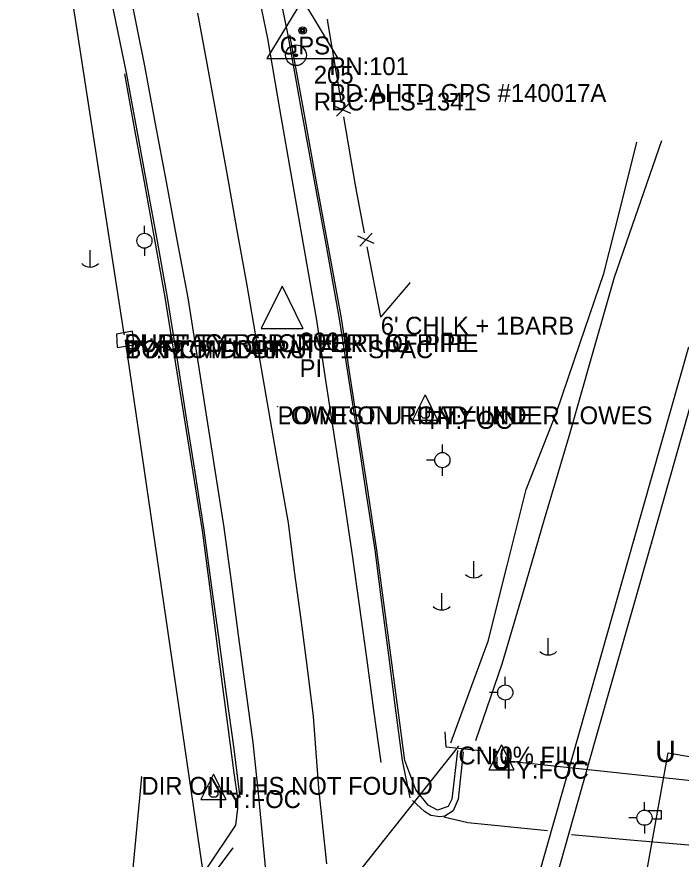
# Model space of a CAD drawing. Extents: x 929765 to 934279, y 1533086 to 1541189.
# Drawn here: x 931911.3 to 932097.7, y 1537538.1 to 1537774.2 of the extents above; entities that cross this region are included whole.
import ezdxf

# ---------------------------------------------------------------- set-up
doc = ezdxf.new("R2010")
doc.units = 0
for name, color, linetype in [('Default', 7, 'Continuous'), ('S_CAL_CORNER', 7, 'Continuous'), ('S_CAL_CORNER_ANNOT', 7, 'Continuous'), ('S_CROSS_DRAIN', 7, 'Continuous'), ('S_CROSS_DRAIN_ANNOT', 7, 'Continuous'), ('S_CURB', 7, 'Continuous'), ('S_DITCHLINE', 7, 'Continuous'), ('S_DRG_PT_SYM', 7, 'Continuous'), ('S_DROP_INLET_ANNOT', 7, 'Continuous'), ('S_EDGE_CONCRETE', 7, 'Continuous'), ('S_EDGE_PAVEMENT', 7, 'Continuous'), ('S_ELECTRIC_UTILITIES_ANNOT', 7, 'Continuous'), ('S_FENCE', 7, 'Continuous'), ('S_FENCE_ANNOT', 7, 'Continuous'), ('S_HEADWALL', 7, 'Continuous'), ('S_IRON_PIN', 7, 'Continuous'), ('S_IRON_PIN_ANNOT', 7, 'Continuous'), ('S_MANHOLE_ANNOT', 7, 'Continuous'), ('S_MSC_PT_SYM', 7, 'Continuous'), ('S_PAVEMENT_CROWN', 7, 'Continuous'), ('S_PRIMARY_CTL', 7, 'Continuous'), ('S_PRIMARY_CTL_ANNOT', 7, 'Continuous'), ('S_RAILROAD', 7, 'Continuous'), ('S_SANITARY_SEWER', 7, 'Continuous'), ('S_SANITARY_SEWER_ANNOT', 7, 'Continuous'), ('S_SHOULDER', 7, 'Continuous'), ('S_STORM_SEWER', 7, 'Continuous'), ('S_STORM_SEWER_ANNOT', 7, 'Continuous'), ('S_SURVEY_TEXT_ANNOT', 7, 'Continuous'), ('S_UNDERGROUND_CABLE', 7, 'Continuous'), ('S_UTILITY_POLE', 7, 'Continuous'), ('S_UTILITY_POLE_ANNOT', 7, 'Continuous'), ('S_UTL_PT_SYM', 7, 'Continuous')]:
    doc.layers.add(name, color=color, linetype=linetype)

msp = doc.modelspace()

# ---------------------------------------------------------------- linework, layer by layer
at = {"layer": 'S_CAL_CORNER'}
for p, q in [((931985.74, 1537698.67), (931979.86, 1537686.85)), ((931985.74, 1537698.67), (931991.55, 1537686.85)), ((931979.86, 1537686.85), (931991.55, 1537686.85))]:
    msp.add_line(p, q, dxfattribs=at)
at = {"layer": 'S_CROSS_DRAIN'}
msp.add_line((931974.13, 1537492.75), (932035.18, 1537569.61), dxfattribs=at)
at = {"layer": 'S_CURB'}
for points in [[(932034.94, 1537568.49), (932033.32, 1537554.86), (932032.3, 1537552.8), (932029.35, 1537551.77), (932026.7, 1537553.15), (932023.25, 1537557.47), (932020.17, 1537565.75), (932018.21, 1537580.48), (932016.25, 1537595.21), (932014.29, 1537609.94), (932012.33, 1537624.67), (932009.84, 1537640.95), (932007.35, 1537657.22), (932004.86, 1537673.5), (932002.37, 1537689.77), (931998.76, 1537709.63), (931995.14, 1537729.49), (931991.53, 1537749.35), (931987.91, 1537769.21)], [(931951.42, 1537526.31), (931964.23, 1537534.86), (931972.76, 1537547.6), (931973.29, 1537552.29), (931973.36, 1537555.14), (931972.31, 1537562.3), (931970.08, 1537579.27), (931967.84, 1537596.25), (931965.61, 1537613.23), (931963.38, 1537630.2), (931960.78, 1537646.56), (931958.18, 1537662.91), (931955.58, 1537679.26), (931952.98, 1537695.61), (931950.14, 1537711.26), (931947.3, 1537726.92), (931944.46, 1537742.57), (931941.62, 1537758.23)]]:
    msp.add_lwpolyline(points, dxfattribs=at)
at = {"layer": 'S_DITCHLINE'}
for points in [[(932033.11, 1537570.71), (932038.34, 1537584.92), (932043.57, 1537599.13), (932048.86, 1537620.42), (932054.15, 1537641.7), (932062.73, 1537663.29), (932069.33, 1537682.77), (932075.94, 1537702.25), (932080.61, 1537720.66), (932085.27, 1537739.06)], [(932040.04, 1537571.29), (932047.46, 1537592.84), (932053.4, 1537613.09), (932059.34, 1537633.33), (932066.26, 1537656.63), (932072.62, 1537678.94), (932078.98, 1537701.25), (932085.6, 1537720.38), (932092.23, 1537739.52)]]:
    msp.add_lwpolyline(points, dxfattribs=at)
at = {"layer": 'S_DRG_PT_SYM'}
for points in [[(931941.81, 1537683.51), (931941.81, 1537683.56), (931941.81, 1537683.51), (931941.76, 1537683.51), (931941.81, 1537683.51), (931941.81, 1537683.46), (931941.81, 1537683.51), (931941.86, 1537683.51)], [(932035.18, 1537569.61), (932035.18, 1537569.66), (932035.18, 1537569.61), (932035.13, 1537569.61), (932035.18, 1537569.61), (932035.18, 1537569.56), (932035.18, 1537569.61), (932035.23, 1537569.61)]]:
    msp.add_lwpolyline(points, dxfattribs=at)
at = {"layer": 'S_EDGE_CONCRETE'}
msp.add_lwpolyline([(931944.22, 1537682.23), (931943.79, 1537686.04), (931939.28, 1537685.21), (931939.51, 1537681.54)], close=True, dxfattribs=at)
msp.add_lwpolyline([(932036.56, 1537568.15), (932035.14, 1537554.86), (932033.7, 1537551.61), (932031.36, 1537550.12), (932029.97, 1537549.91), (932027.45, 1537550.32), (932025.68, 1537551.39), (932022.31, 1537554.46)], dxfattribs=at)
at = {"layer": 'S_EDGE_PAVEMENT'}
for points in [[(931981.22, 1537534.96), (931979.16, 1537556.54), (931977.64, 1537570.72), (931975.6, 1537585.79), (931973.55, 1537600.86), (931971.51, 1537615.93), (931969.46, 1537631), (931966.94, 1537647.11), (931964.42, 1537663.22), (931961.89, 1537679.33), (931959.37, 1537695.44), (931956.33, 1537711.7), (931953.29, 1537727.95), (931950.25, 1537744.2), (931947.21, 1537760.45), (931942.74, 1537782.82), (931938.28, 1537805.2), (931934.64, 1537822.05), (931931, 1537838.9), (931927.36, 1537855.75), (931923.72, 1537872.6), (931920.41, 1537886.31), (931917.1, 1537900.03)], [(932013.54, 1537565.12), (932011.5, 1537579.83), (932009.47, 1537594.54), (932007.44, 1537609.25), (932005.4, 1537623.96), (932002.92, 1537640.28), (932000.43, 1537656.59), (931997.95, 1537672.9), (931995.46, 1537689.21), (931992.02, 1537708.93), (931988.58, 1537728.65), (931985.14, 1537748.37), (931981.7, 1537768.09), (931979.05, 1537781.28), (931976.4, 1537794.47), (931973.75, 1537807.66), (931971.1, 1537820.85), (931967.73, 1537835.84), (931964.36, 1537850.82), (931961, 1537865.81), (931957.63, 1537880.8), (931954.49, 1537894.12)], [(932060.14, 1537545.98), (932037.8, 1537548.24), (932031.11, 1537549.86)], [(932132.45, 1537539.14), (932116.07, 1537540.56), (932099.7, 1537541.99), (932083.32, 1537543.41), (932066.94, 1537544.83)], [(931953.05, 1537524.89), (931963.67, 1537532.14), (931967.87, 1537535.71), (931972.01, 1537541.26)]]:
    msp.add_lwpolyline(points, dxfattribs=at)
at = {"layer": 'S_FENCE'}
for p, q in [((932000.96, 1537746.38), (932004.51, 1537749.9)), ((932000.96, 1537746.38), (932004.51, 1537749.9)), ((932005, 1537747.07), (932000.48, 1537749.21)), ((932005, 1537747.07), (932000.48, 1537749.21)), ((932011.54, 1537710.7), (932006.97, 1537712.74)), ((932011.54, 1537710.7), (932006.97, 1537712.74)), ((932007.51, 1537709.93), (932011, 1537713.52)), ((932007.51, 1537709.93), (932011, 1537713.52))]:
    msp.add_line(p, q, dxfattribs=at)
for points in [[(932002.4, 1537750.11), (931998.44, 1537773.39)], [(932002.4, 1537750.11), (931998.44, 1537773.39)], [(932006.42, 1537726.45), (932003.07, 1537746.17)], [(932006.42, 1537726.45), (932003.07, 1537746.17)], [(932008.88, 1537713.69), (932006.42, 1537726.45)], [(932008.88, 1537713.69), (932006.42, 1537726.45)], [(932013.41, 1537690.12), (932009.63, 1537709.76)], [(932013.41, 1537690.12), (932009.63, 1537709.76)], [(932021.53, 1537699.62), (932013.41, 1537690.12)], [(932021.53, 1537699.62), (932013.41, 1537690.12)]]:
    msp.add_lwpolyline(points, dxfattribs=at)
at = {"layer": 'S_HEADWALL'}
msp.add_lwpolyline([(932042.11, 1537568.36), (932031.77, 1537569.49), (932031.45, 1537573.75)], dxfattribs=at)
at = {"layer": 'S_IRON_PIN'}
for radius in [2.91, 0.411, 0.262, 0.212, 0.145, 0.0822, 0.0581]:
    msp.add_circle((931989.63, 1537763.45), radius, dxfattribs=at)
at = {"layer": 'S_MSC_PT_SYM'}
for points in [[(931998.44, 1537773.39), (931998.44, 1537773.44), (931998.44, 1537773.39), (931998.39, 1537773.39), (931998.44, 1537773.39), (931998.44, 1537773.34), (931998.44, 1537773.39), (931998.49, 1537773.39)], [(932006.42, 1537726.45), (932006.42, 1537726.5), (932006.42, 1537726.45), (932006.37, 1537726.45), (932006.42, 1537726.45), (932006.42, 1537726.4), (932006.42, 1537726.45), (932006.47, 1537726.45)], [(932021.53, 1537699.62), (932021.53, 1537699.67), (932021.53, 1537699.62), (932021.48, 1537699.62), (932021.53, 1537699.62), (932021.53, 1537699.57), (932021.53, 1537699.62), (932021.58, 1537699.62)], [(932013.41, 1537690.12), (932013.41, 1537690.17), (932013.41, 1537690.12), (932013.36, 1537690.12), (932013.41, 1537690.12), (932013.41, 1537690.07), (932013.41, 1537690.12), (932013.46, 1537690.12)], [(931941.47, 1537685.23), (931941.47, 1537685.28), (931941.47, 1537685.23), (931941.42, 1537685.23), (931941.47, 1537685.23), (931941.47, 1537685.18), (931941.47, 1537685.23), (931941.52, 1537685.23)], [(931984.48, 1537664.99), (931984.48, 1537665.04), (931984.48, 1537664.99), (931984.43, 1537664.99), (931984.48, 1537664.99), (931984.48, 1537664.94), (931984.48, 1537664.99), (931984.53, 1537664.99)], [(932084.46, 1537627.73), (932084.46, 1537627.78), (932084.46, 1537627.73), (932084.41, 1537627.73), (932084.46, 1537627.73), (932084.46, 1537627.68), (932084.46, 1537627.73), (932084.51, 1537627.73)], [(932089.34, 1537626.62), (932089.34, 1537626.67), (932089.34, 1537626.62), (932089.29, 1537626.62), (932089.34, 1537626.62), (932089.34, 1537626.57), (932089.34, 1537626.62), (932089.39, 1537626.62)], [(932069.38, 1537574.33), (932069.38, 1537574.38), (932069.38, 1537574.33), (932069.33, 1537574.33), (932069.38, 1537574.33), (932069.38, 1537574.28), (932069.38, 1537574.33), (932069.43, 1537574.33)], [(932073.74, 1537571.91), (932073.74, 1537571.96), (932073.74, 1537571.91), (932073.69, 1537571.91), (932073.74, 1537571.91), (932073.74, 1537571.86), (932073.74, 1537571.91), (932073.79, 1537571.91)]]:
    msp.add_lwpolyline(points, dxfattribs=at)
at = {"layer": 'S_PAVEMENT_CROWN'}
msp.add_lwpolyline([(931998.24, 1537536.73), (931996.02, 1537557.94), (931994.59, 1537578.02), (931992.82, 1537591.62), (931991.04, 1537605.21), (931989.26, 1537618.8), (931987.49, 1537632.39), (931984.58, 1537649.15), (931981.68, 1537665.91), (931978.77, 1537682.67), (931975.87, 1537699.43), (931973.08, 1537714.85), (931970.29, 1537730.26), (931967.5, 1537745.68), (931964.71, 1537761.1), (931962.08, 1537775.23)], dxfattribs=at)
at = {"layer": 'S_PRIMARY_CTL'}
for p, q in [((931991.5, 1537779.07), (931981.47, 1537762.56)), ((931991.5, 1537779.07), (932001.33, 1537762.56)), ((931981.47, 1537762.56), (932001.33, 1537762.56))]:
    msp.add_line(p, q, dxfattribs=at)
for radius in [1.04, 0.609, 0.344]:
    msp.add_circle((931991.5, 1537770.37), radius, dxfattribs=at)
at = {"layer": 'S_RAILROAD'}
for p, q in [((932084.46, 1537627.73), (932099.81, 1537681.72)), ((932089.34, 1537626.62), (932104.37, 1537679.83)), ((932069.38, 1537574.33), (932084.46, 1537627.73)), ((932073.74, 1537571.91), (932089.34, 1537626.62)), ((932053.49, 1537518.73), (932069.38, 1537574.33)), ((932058.32, 1537517.56), (932073.74, 1537571.91)), ((932087.37, 1537551.78), (932087.37, 1537554.03)), ((932092.17, 1537551.63), (932088.3, 1537551.63)), ((932092.17, 1537549.3), (932092.17, 1537551.63)), ((932085.27, 1537549.65), (932082.95, 1537549.65)), ((932092.17, 1537549.3), (932089.46, 1537549.3)), ((932087.44, 1537545.23), (932087.44, 1537547.56))]:
    msp.add_line(p, q, dxfattribs=at)
msp.add_circle((932087.37, 1537549.67), 2.13, dxfattribs=at)
at = {"layer": 'S_SANITARY_SEWER'}
msp.add_line((931946.28, 1537561.11), (931939.08, 1537485.09), dxfattribs=at)
at = {"layer": 'S_SHOULDER'}
for points in [[(931973.95, 1537555.3), (931972.29, 1537569.03), (931970.18, 1537584.34), (931968.08, 1537599.65), (931965.97, 1537614.96), (931963.87, 1537630.27), (931961.31, 1537646.59), (931958.75, 1537662.9), (931956.19, 1537679.22), (931953.63, 1537695.53), (931950.75, 1537711.28), (931947.86, 1537727.03), (931944.98, 1537742.78), (931942.1, 1537758.53), (931937.34, 1537781.66), (931932.57, 1537804.8), (931928.93, 1537821.29), (931925.29, 1537837.78), (931921.65, 1537854.27), (931918.01, 1537870.76), (931914.67, 1537884.32), (931911.34, 1537897.89)], [(932021.69, 1537555.26), (932019.48, 1537565.71), (932017.57, 1537580.47), (932015.65, 1537595.24), (932013.73, 1537610), (932011.81, 1537624.76), (932009.32, 1537640.96), (932006.84, 1537657.16), (932004.35, 1537673.35), (932001.86, 1537689.55), (931998.25, 1537709.42), (931994.64, 1537729.29), (931991.03, 1537749.16), (931987.42, 1537769.03), (931984.69, 1537782.3), (931981.96, 1537795.57), (931979.23, 1537808.84), (931976.5, 1537822.11), (931973.12, 1537837.06), (931969.73, 1537852), (931966.34, 1537866.94), (931962.96, 1537881.88), (931959.83, 1537895.3)]]:
    msp.add_lwpolyline(points, dxfattribs=at)
at = {"layer": 'S_STORM_SEWER'}
for p, q in [((931941.47, 1537685.23), (931921.9, 1537812)), ((931969.37, 1537495.1), (931941.79, 1537683.51))]:
    msp.add_line(p, q, dxfattribs=at)
at = {"layer": 'S_UNDERGROUND_CABLE'}
for p, q in [((932025.84, 1537668.23), (932022.32, 1537661.14)), ((932025.84, 1537668.23), (932029.33, 1537661.14)), ((932024.64, 1537662.38), (932024.64, 1537664.82)), ((932027.01, 1537664.82), (932027.01, 1537662.38)), ((932025.26, 1537661.72), (932024.64, 1537662.38)), ((932027.01, 1537662.38), (932026.46, 1537661.72)), ((932022.32, 1537661.14), (932029.33, 1537661.14)), ((932026.46, 1537661.72), (932025.26, 1537661.72)), ((932047.23, 1537570.15), (932043.71, 1537563.06)), ((932047.23, 1537570.15), (932050.72, 1537563.06)), ((932046.03, 1537564.3), (932046.03, 1537566.74)), ((932134.61, 1537556.35), (932047.91, 1537565.6)), ((932048.4, 1537566.74), (932048.4, 1537564.3)), ((932081.62, 1537499.31), (932094.03, 1537567.82)), ((932094.03, 1537567.82), (932136.59, 1537560.67)), ((932046.65, 1537563.64), (932046.03, 1537564.3)), ((932047.85, 1537563.64), (932046.65, 1537563.64)), ((932048.4, 1537564.3), (932047.85, 1537563.64)), ((931966.5, 1537561.91), (931962.98, 1537554.82)), ((931966.5, 1537561.91), (931969.99, 1537554.82)), ((932043.71, 1537563.06), (932050.72, 1537563.06)), ((931965.3, 1537556.06), (931965.3, 1537558.5)), ((931967.67, 1537558.5), (931967.67, 1537556.06)), ((931965.92, 1537555.4), (931965.3, 1537556.06)), ((931967.67, 1537556.06), (931967.12, 1537555.4)), ((931962.98, 1537554.82), (931969.99, 1537554.82)), ((931967.12, 1537555.4), (931965.92, 1537555.4))]:
    msp.add_line(p, q, dxfattribs=at)
at = {"layer": 'S_UTILITY_POLE'}
for p, q in [((931947.11, 1537713.52), (931947.11, 1537715.65)), ((931931.82, 1537708.78), (931931.82, 1537704.05)), ((931947.11, 1537709.3), (931947.11, 1537707.25)), ((932030.69, 1537652.05), (932030.69, 1537654.3)), ((932028.6, 1537649.92), (932026.28, 1537649.92)), ((932030.77, 1537645.5), (932030.77, 1537647.83)), ((932039.45, 1537621.64), (932039.45, 1537616.91)), ((932030.43, 1537612.62), (932030.43, 1537607.9)), ((932060.31, 1537600.02), (932060.31, 1537595.3)), ((932048.34, 1537586.88), (932048.34, 1537589.13)), ((932046.25, 1537584.75), (932043.92, 1537584.75)), ((932048.42, 1537580.33), (932048.42, 1537582.66))]:
    msp.add_line(p, q, dxfattribs=at)
for centre, radius in [((931947.13, 1537711.44), 2.11), ((932030.7, 1537649.94), 2.13), ((932048.34, 1537584.77), 2.13)]:
    msp.add_circle(centre, radius, dxfattribs=at)
for centre in [(931931.88, 1537707.48), (932039.51, 1537620.33), (932030.49, 1537611.32), (932060.37, 1537598.72)]:
    msp.add_arc(centre, 3.41, 226.3972, 313.6028, dxfattribs=at)
at = {"layer": 'S_UTL_PT_SYM'}
for points in [[(931941.47, 1537685.23), (931941.47, 1537685.28), (931941.47, 1537685.23), (931941.42, 1537685.23), (931941.47, 1537685.23), (931941.47, 1537685.18), (931941.47, 1537685.23), (931941.52, 1537685.23)], [(931941.79, 1537683.51), (931941.79, 1537683.56), (931941.79, 1537683.51), (931941.74, 1537683.51), (931941.79, 1537683.51), (931941.79, 1537683.46), (931941.79, 1537683.51), (931941.84, 1537683.51)], [(931941.8, 1537683.52), (931941.8, 1537683.57), (931941.8, 1537683.52), (931941.75, 1537683.52), (931941.8, 1537683.52), (931941.8, 1537683.47), (931941.8, 1537683.52), (931941.85, 1537683.52)], [(931984.48, 1537664.99), (931984.48, 1537665.04), (931984.48, 1537664.99), (931984.43, 1537664.99), (931984.48, 1537664.99), (931984.48, 1537664.94), (931984.48, 1537664.99), (931984.53, 1537664.99)], [(931946.28, 1537561.11), (931946.28, 1537561.16), (931946.28, 1537561.11), (931946.23, 1537561.11), (931946.28, 1537561.11), (931946.28, 1537561.06), (931946.28, 1537561.11), (931946.33, 1537561.11)]]:
    msp.add_lwpolyline(points, dxfattribs=at)

# ---------------------------------------------------------------- texts
at = {"layer": 'Default'}
for p in [(932090.4, 1537565.27), (932044.28, 1537563.06)]:
    msp.add_text('U', height=6, rotation=360, dxfattribs=at).set_placement(p)
at = {"layer": 'S_CAL_CORNER_ANNOT'}
for s, p in [('2001', (931990.65, 1537680.69)), ('PI', (931990.65, 1537673.19))]:
    msp.add_text(s, height=5, dxfattribs=at).set_placement(p)
at = {"layer": 'S_CROSS_DRAIN_ANNOT'}
msp.add_text('CN:0% FILL', height=5, dxfattribs=at).set_placement((932035.18, 1537564.61))
at = {"layer": 'S_DROP_INLET_ANNOT'}
msp.add_text('2\' X 2\' MTL GRATE 1" SPAC', height=5, dxfattribs=at).set_placement((931941.81, 1537678.51))
at = {"layer": 'S_ELECTRIC_UTILITIES_ANNOT'}
msp.add_text('LOWEST UTILITY LINE', height=5, dxfattribs=at).set_placement((931984.48, 1537659.99))
at = {"layer": 'S_FENCE_ANNOT'}
msp.add_text("6' CHLK + 1BARB", height=5, dxfattribs=at).set_placement((932013.41, 1537685.12))
at = {"layer": 'S_IRON_PIN_ANNOT'}
for s, p in [('205', (931994.63, 1537755.45)), ('RBC PLS-1341', (931994.63, 1537747.95))]:
    msp.add_text(s, height=5, dxfattribs=at).set_placement(p)
at = {"layer": 'S_MANHOLE_ANNOT'}
msp.add_text('BOTTOM OF PU', height=5, dxfattribs=at).set_placement((931941.8, 1537678.52))
at = {"layer": 'S_PRIMARY_CTL'}
msp.add_text('GPS', height=5, rotation=360, dxfattribs=at).set_placement((931985.06, 1537763.67))
at = {"layer": 'S_PRIMARY_CTL_ANNOT'}
for s, p in [('PN:101', (931999, 1537757.87)), ('PD:AHTD GPS #140017A', (931999, 1537750.37))]:
    msp.add_text(s, height=5, dxfattribs=at).set_placement(p)
at = {"layer": 'S_SANITARY_SEWER_ANNOT'}
msp.add_text('DIR ONLI HS NOT FOUND', height=5, dxfattribs=at).set_placement((931946.28, 1537556.11))
at = {"layer": 'S_STORM_SEWER_ANNOT'}
for s, p in [('TY:RCP DI:48"', (931941.79, 1537678.51)), ('DI:45" TY:RCP INVERT OF PIPE', (931941.47, 1537680.23))]:
    msp.add_text(s, height=5, dxfattribs=at).set_placement(p)
at = {"layer": 'S_SURVEY_TEXT_ANNOT'}
for s, p in [('SURFACE SHOT FOR UG PIPE', (931941.47, 1537680.23)), ('POINT ON ROAD UNDER LOWES', (931984.48, 1537659.99))]:
    msp.add_text(s, height=5, dxfattribs=at).set_placement(p)
at = {"layer": 'S_UTILITY_POLE_ANNOT'}
for p in [(932025.84, 1537658.7), (932047.23, 1537560.62), (931966.5, 1537552.38)]:
    msp.add_text('TY:FOC', height=5, dxfattribs=at).set_placement(p)

doc.saveas('drawing.dxf')
